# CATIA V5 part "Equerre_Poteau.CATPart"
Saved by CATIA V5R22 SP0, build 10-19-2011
Part number: Equerre_Poteau
Bounding box of the stored display mesh (mm): x -31.5 to 31.5, y -20 to 20, z 0 to 42
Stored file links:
  U:\S9A\PER\CAO\Assemblage\Cadre\Poteau\Equerre_Poteau.CATPart
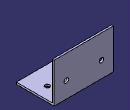
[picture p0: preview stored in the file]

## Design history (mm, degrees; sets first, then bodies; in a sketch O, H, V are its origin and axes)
Body1 (main body)
  Sketch1 on xy-plane, origin (0, 0, 0), H (1, 0, 0), V (0, 1, 0)
    point P1 (-31.5, 20)
    line L1 (-31.5, 20) -> (31.5, 20)
    line L2 (31.5, 20) -> (31.5, -20)
    line L3 (31.5, -20) -> (-31.5, -20)
    line L4 (-31.5, -20) -> (-31.5, 20)
    point P2 (31.5, 20)
    point P3 (31.5, -20)
    point P4 (-31.5, -20)
    length L1 = 63
    length L2 = 40
    horizontal: L1 H, L3 H
    vertical: L2 V, L4 V
    equidistance: P3 P1 O, P2 P4 O
  Pad1: profile Sketch1, direction (0, 0, 1), length 2
  Sketch2 on end face of Pad1, origin (0, 0, 2), H (1, 0, 0), V (0, 1, 0)
    line L1 (-31.5, 20) -> (31.5, 20)
    line L2 (31.5, 20) -> (31.5, 18)
    line L3 (31.5, 18) -> (-31.5, 18)
    line L4 (-31.5, 18) -> (-31.5, 20)
    reference projected line E1 (31.5, 20) -> (-31.5, 20) from edge [face of Pad1 from Sketch1.L1 | end face of Pad1]
    reference projected line E2 (-31.5, 20) -> (-31.5, -20) from edge [face of Pad1 from Sketch1.L4 | end face of Pad1]
    reference projected line E3 (31.5, -20) -> (31.5, 20) from edge [face of Pad1 from Sketch1.L2 | end face of Pad1]
    length L4 = 2
    horizontal: L1 H, L3 H
    vertical: L2 V, L4 V
    coincidence: L1 E1, L4 E2, L2 E3
  Pad2: profile Sketch2, direction (0, 0, 1), length 40
  Sketch3 on end face of Pad1, origin (13.9583, 2.0203, 2), H (1, 0, 0), V (0, 1, 0)
    point P1 (4.5417, -2.0203)
    reference projected line E1 (-45.4583, 15.9797) -> (17.5417, 15.9797) from edge [face of Pad2 from Sketch2.L3 | end face of Pad2]
    reference projected line E2 (17.5417, -22.0203) -> (17.5417, 17.9797) from edge [face of Pad2 | end face of Pad1]
    distance P1 E1 = 18
    distance P1 E2 = 13
  Hole1: placed by Sketch3, at (18.5, 0, 2) direction (0, 0, -1), diameter 5, through (limit type 3)
  RectPattern1: of Hole1, direction 1 instances 2, spacing 37, along end face of Pad1 reversed
  Sketch4 on face of Pad2 from Sketch2.L3, origin (-8.7361, 18, 23.2748), H (1, 0, 0), V (0, 0, 1)
    point P1 (-9.7639, -6.2748)
    reference projected line E1 (-22.7639, -23.2748) -> (40.2361, -23.2748) from edge [start face of Pad1 | face of Pad1 from Sketch1.L3]
    reference projected line E2 (-22.7639, -21.2748) -> (-22.7639, 18.7252) from edge [face of Pad2 from Sketch2.L3 | face of Pad2]
    distance P1 E1 = 17
    distance P1 E2 = 13
  Hole2: placed by Sketch4, at (-18.5, 18, 17) direction (0, 1, 0), diameter 5, through (limit type 3)
  RectPattern2: of Hole2, direction 1 instances 2, spacing 37, along face of Pad2 from Sketch2.L3 reversed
